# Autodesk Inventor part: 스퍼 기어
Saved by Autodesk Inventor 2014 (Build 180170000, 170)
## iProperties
Created: 2025-10
Part Number: 스퍼 기어
Material: 일반
Document SubType Name: Modeling
Designer: dg
Density: 1 g/cm^3
Appearance: 기본값
Author: dg
Author: jhkim
Creation Date: 2025-10-01
Sending System: Autodesk Inventor 2026
Preprocessor: ST-DEVELOPER v20.1
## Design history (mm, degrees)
node "스퍼 기어1"
node "솔리드1"
node "기준1"
